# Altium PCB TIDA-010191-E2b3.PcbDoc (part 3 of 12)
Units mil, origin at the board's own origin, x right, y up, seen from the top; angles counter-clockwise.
Board outline 9842.52 x 9842.4 mil, 6 copper layers (Layer 1 - Top Layer, Layer 2 - GND Layer, Layer 3 - Signal, Layer 4 - Signal, Layer 5 - GND, Bottom Layer), stack 59.9 mil thick; 1178 components, 642 nets, 3329 pads, 2967 vias.
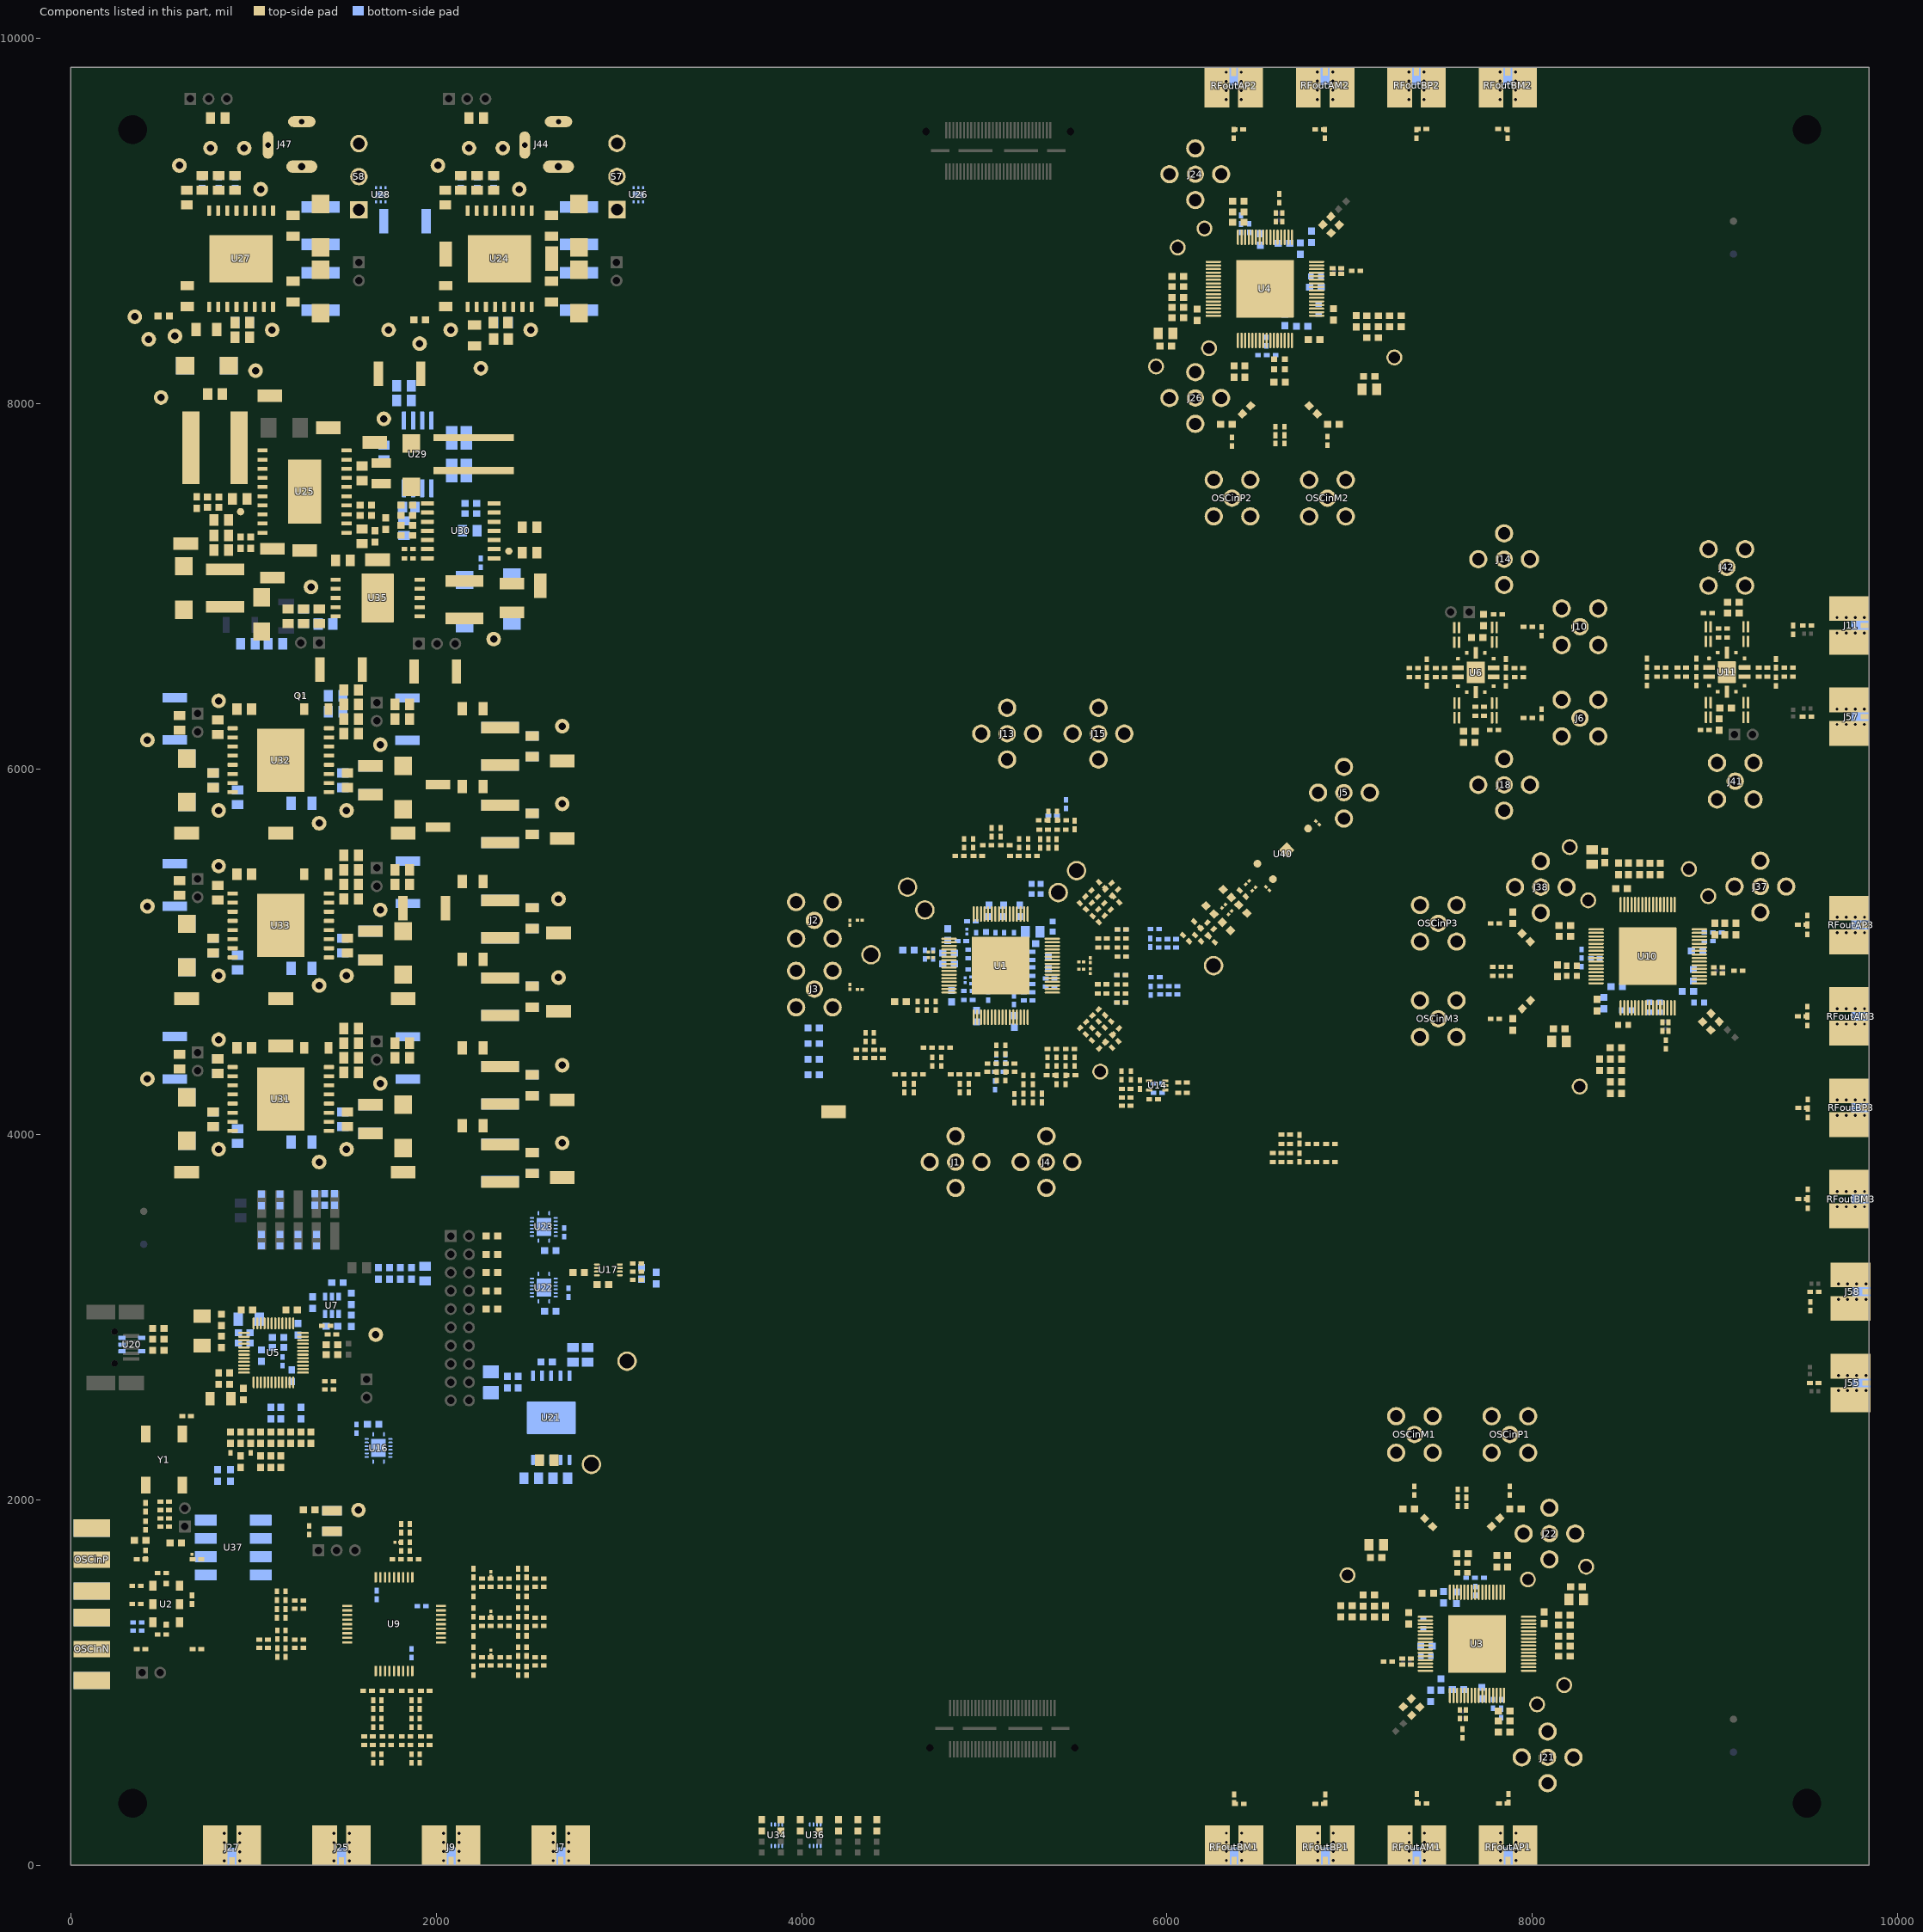
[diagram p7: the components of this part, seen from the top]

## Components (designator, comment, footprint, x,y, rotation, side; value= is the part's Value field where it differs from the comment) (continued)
OSCinP1 "142-0701-201" Johnson_142-0701-20x 7876.55,2358.61 r270 top
OSCinP2 "142-0701-201" Johnson_142-0701-20x 6355.8,7484.37 r90 top
OSCinP3 "CMP-0055819-1" Johnson_142-0701-20x 7484.87,5156.75 r0 top
Q1 "MMBT3904LP" DIODES_X1-DFN1006-3 1262.75,6401.42 r180 top value="40 V"
R1 "Resistor" 0402 5040,4344 r180 top value=0
R2 "Resistor" 0402 5425,5721 r0 top value=0
R3 "Resistor" 0402 5068,4320 r90 top value=0
R4 "Resistor" 0402 4915,4255 r270 top value=0
R5 "Resistor" 0402 5215,4300 r90 top value=120
R6 "Resistor" 0402 5115,4320 r90 top value=0
R7 "Resistor" 0402 4865,4255 r270 top value=0
R8 "Resistor" 0402 5215.21,4200.32 r270 top value=0
R9 "Resistor" 0402 5143,4344 r0 top value=0
R10 "Resistor" 0402 5322,5721 r180 top value=0
R11 "Resistor" 0402 5141,4390 r180 top value=240
R12 "Resistor" 0402 5041,4390 r0 top value=240
R13 "Resistor" 0402 5315.21,4200.32 r90 top value=120
R14 "Resistor" 0402 5165,4200 r90 top value=120
R15 "Resistor" 0402 4940,4330 r180 top value=240
R16 "Resistor" 0402 4840,4330 r0 top value=240
R17 "Resistor" 0402 4790,4475 r180 top value=220
R18 "Resistor" 0402 4690,4475 r0 top value=220
R19 "Resistor" 0402 4613,4255 r270 top value=0
R20 "Resistor" 0402 4563,4255 r270 top value=0
R21 "Resistor" 0402 5470,4470 r180 top value=120
R22 "Resistor" 0402 5370,4470 r0 top value=120
R23 "Resistor" 0402 4640.72,4331.16 r180 top value=240
R24 "Resistor" 0402 4535.72,4331.16 r0 top value=240
R25 "Resistor" 0402 5749.89,4773.09 r0 top value=0
R26 "CMP-0026822-3" 0402 5645.83,4488.44 r45 top value=0
R27 "Resistor" 0402 5750,4823 r0 top value=0
R28 "Resistor" 0201 4940,4826.66 r180 bottom value=620
R29 "Resistor" 0402 5749.89,4873.09 r180 top value=120
R30 "Resistor" 0402 5749.89,4723.09 r180 top value=120
R31 "Resistor" 0402 5608.61,4668.61 r225 top value=120
R32 "Resistor" 0402 5540.8,4600 r45 top value=120
R33 "Resistor" 0402 635,2460 r0 top value=0
R34 "Resistor" 0402 1175,1379 r270 top value=130
R35 "Resistor" 0402 5240,4735 r0 bottom value=10.0k
R36 "ERJ-2GE0R00X" 0402 1250,1405 r0 top value=0
R37 "Resistor" 0402 385,1183.92 r0 top value=0
R38 "ERJ-2GE0R00X" 0402 1250,1450 r0 top value=0
R39 "Resistor" 0402 385,1675 r0 top value=0
R40 "Resistor" 0402 1175,1476 r90 top value=130
R41 "Resistor" 0402 5751.89,5024.09 r0 top value=0
R42 "Resistor" 0402 5751.89,5074.09 r0 top value=0
R43 "Resistor" 0402 499.09,1263.12 r180 top value=12k
R44 "Resistor" 0402 500,1600 r180 top value=12k
R45 "Resistor" 0402 360,1530 r180 top value=0
R46 "Resistor" 0402 360,1430 r180 top value=0
R47 "Resistor" 0402 5540,5250 r315 top value=120
R48 "Resistor" 0402 5610,5180 r135 top value=120
R49 "Resistor" 0402 5751.89,5124.09 r180 top value=120
R50 "Resistor" 0402 5751.89,4974.09 r180 top value=120
R51 "Resistor" 0402 664.09,1454.12 r270 top value=12k
R52 "Resistor" 0201 4905,5111.3 r90 bottom value=39.0k
R53 "Resistor" 0603L 5010,5081.38 r270 bottom value=51
R54 "Resistor" 0402 5397,5745 r270 top value=0
R55 "Resistor" 0402 4890,5595 r90 top value=0
R56 "Resistor" 0402 5350,5745 r270 top value=0
R57 "Resistor" 0402 4940,5595 r90 top value=0
R58 "Resistor" 0402 5325,5670 r0 top value=220
R59 "Resistor" 0402 5423,5670 r180 top value=220
R60 "Resistor" 0402 4865,5525 r180 top value=240
R61 "Resistor" 0402 4965,5525 r0 top value=240
R62 "Resistor" 0402 5240,5595 r270 top value=0
R63 "Resistor" 0402 5190,5595 r270 top value=0
R64 "Resistor" 0402 5165,5525 r180 top value=240
R65 "Resistor" 0402 5265,5525 r0 top value=240
R66 "Resistor" 0402 5015,5585 r0 top value=240
R67 "Resistor" 0402 5115,5585 r180 top value=240
R68 "CMP-0026822-3" 0402 5682,4493 r135 top value=0
R69 "CMP-0026822-3" 0402 5720.91,4565.5 r225 top value=0
R70 "Resistor" 0402 4765,4400 r270 top value=0
R71 "CMP-0026822-3" 0402 5717,4528 r135 top value=0
R72 "CMP-0026822-3" 0402 6033.51,4767.92 r180 bottom value=0
R73 "CMP-0026822-3" 0402 6033.51,4812.92 r180 bottom value=0
R74 "CMP-0026822-3" 0402 5721.7,5287.74 r135 top value=0
R75 "CMP-0026822-3" 0402 5715,5325 r225 top value=0
R76 "CMP-0026822-3" 0402 5644.59,5365.44 r315 top value=0
R77 "Resistor" 0603 4066.89,4412 r180 bottom value=750
R78 "Resistor" 0603 4066.89,4328.46 r180 bottom value=750
R79 "Resistor" 0603 4066.89,4583.46 r180 bottom value=750
R80 "Resistor" 0603 4066.89,4498.46 r180 bottom value=750
R81 "CMP-0026822-3" 0402 5680,5360 r225 top value=0
R82 "CMP-0026791-1" 0402 7634.77,827.47 r270 top value=50
R83 "Resistor" 0603 7512.98,1467.65 r270 bottom value=0
R84 "CMP-0026822-3" 0402 6025.96,5025.26 r180 bottom value=0
R85 "Resistor" 0603L 7402.35,1322.98 r270 bottom value=0
R86 "CMP-0026791-1" 0402 7602.4,827.46 r90 top value=50
R87 "Resistor" 0603 7500,990 r270 bottom value=0
R88 "Resistor" 0603L 7416.87,1146.12 r180 bottom value=0
R89 "Resistor" 0603 7845,730 r0 top value=0
R90 "Resistor" 0603 7865,1665 r270 top value=100k
R91 "Resistor" 0603 8175,1370 r0 top value=0
R92 "CMP-0026822-3" 0402 6025.96,5070.26 r180 bottom value=0
R93 "CMP-0026791-1" 0402 7310.77,1131.8 r180 top value=50
R94 "Resistor" 0603 7105,1480 r180 top value=270
R95 "CMP-0025697-4" 0603 7105,1420 r180 top value=0
R96 "Resistor" 0603 6982.45,1360.54 r180 top value=120
R97 "CMP-0026791-1" 0402 7310.77,1099.43 r0 top value=50
R98 "CMP-0065361-1" 0201 4318.74,5174.45 r0 top value=0
R99 "RC0201JR-0751RL" 0201 4265,5160 r90 top value=51
R100 "RC0201JR-0751RL" 0201 4263.74,4809.72 r90 top value=51
R101 "CMP-0065361-1" 0201 4318.74,4793.74 r0 top value=0
R102 "CMP-0021991-4" 0603 7314.86,890.31 r225 top value=100
R103 "ERJ-1GN0R00C" 0201 6345,5215 r225 top value=0
R104 "Resistor" 0603 7907.35,1951.61 r0 top value=51
R105 "Resistor" 0603 7361.15,844.02 r45 top value=330
R106 "ERJ-1GN0R00C" 0201 6824,5706 r315 top value=0
R107 "Resistor" 0603 7798.75,1878.01 r225 top value=0
R108 "CRCW060349R9FKEA" 0603 6415,5235 r135 top value=49.9
R109 "CMP-0021991-4" 0603 7617.35,1705.61 r0 top value=100
R110 "CRCW060349R9FKEA" 0603 6325,5140 r135 top value=49.9
R111 "ERJ-1GN0R00C" 0201 6475,5345 r225 top value=0
R112 "Resistor" 0603 7431.75,1877.01 r135 top value=0
R113 "Resistor" 0603 7322.35,1951.61 r0 top value=51
R114 "Resistor" 0402 5675,5215 r45 top value=0
R115 "Resistor" 0402 5751.89,5124.09 r180 bottom value=0
R116 "CRCW0402100RFKED" 0402 6415,5320 r315 top value=100
R117 "ERJ-1GN0R00C" 0201 6440,5380 r225 top value=0
R118 "CRCW060349R9FKEA" 0603 6330,5320 r135 top value=49.9
R119 "CRCW060349R9FKEA" 0603 6235,5230 r135 top value=49.9
R120 "ERJ-1GN0R00C" 0201 6310,5250 r225 top value=0
R121 "CRCW040240R2FKED" 0402 7350,6505 r180 top value=40.2
R122 "CRCW0402200RFKED" 0402 7855,6480 r270 top value=200
R123 "CRCW04021K10JNED" 0402 8050,6305 r270 top value=1.1k
R124 "CRCW040212R1FKED" 0402 7926.31,6505 r180 top value=12.1
R125 "CRCW040212R1FKED" 0402 7925,6555 r180 top value=12.1
R126 "CMP-0026822-3" 0402 5365,4325 r0 top value=0
R127 "CMP-0026822-3" 0402 5395,4300 r90 top value=0
R128 "CRCW0402200RFKED" 0402 7855,6580 r90 top value=200
R129 "CRCW04021K10JNED" 0402 8050,6755 r90 top value=1.1k
R130 "CMP-0026822-3" 0402 5475,4325 r180 top value=0
R131 "CRCW040240R2FKED" 0402 7350,6555 r180 top value=40.2
R132 "CMP-0026822-3" 0402 5445,4300 r90 top value=0
R133 "CRCW04020000Z0ED" 0402 7811.31,6847.18 r180 top value=0
R134 "CRCW04020000Z0ED" 0402 7790,6215 r180 top value=0
R135 "CMP-0026822-3" 0402 6602.76,3850 r0 top value=0
R136 "CMP-0026822-3" 0402 6602.76,3900 r0 top value=0
R137 "CRCW06031K00FKEA" 0603 7654.31,6207.18 r0 top value=1.00k
R138 "CRCW060349R9FKEA" 0603 7698,6721 r180 top value=49.9
R139 "ERJ-2RKF1002X" 0402 7711.31,6292.18 r180 top value=10.0k
R140 "CRCW06031K00FKEA" 0603 7653.94,6146.75 r0 top value=1.00k
R141 "Resistor" 0402 5058.62,4269.47 r90 bottom value=0
R142 "Resistor" 0402 5936.27,4862.92 r180 bottom value=0
R143 "CRCW0402100RFKED" 0402 5080.9,4343.12 r180 bottom value=100
R144 "Resistor" 0402 6895,3950 r0 top value=0
R145 "CRCW0402100RFKED" 0402 6169.89,5075 r135 top value=100
R146 "Resistor" 0402 6650,3900 r0 top value=0
R147 "Resistor" 0603 1430,2795.59 r0 top value=39k
R148 "Resistor" 0402 6895,3850 r0 top value=0
R149 "Resistor" 0603 480,2880 r0 top value=10.0
R150 "Resistor" 0603 480,2820 r0 top value=10.0
R151 "Resistor" 0603 1095,2475.59 r90 bottom value=10k
R152 "Resistor" 0603 1150,2475.59 r90 bottom value=10k
R153 "CMP-0025711-4" 0603 1045,2790 r270 bottom value=12k
R154 "CMP-0021991-4" 0603 930,2340.59 r270 top value=100
R155 "CRCW04024K75FKED" 0402 1430,2905.59 r0 top value=4.75k
R156 "CMP-0021991-4" 0603 1040,2340.59 r270 top value=100
R157 "CMP-0021991-4" 0603 1095,2340.59 r270 top value=100
R158 "CMP-0021991-4" 0603 1150,2340.59 r270 top value=100
R159 "CMP-0021991-4" 0603 1205,2340.59 r270 top value=100
R160 "Resistor" 0603 1535,2980.59 r90 bottom value=10k
R161 "Resistor" 0603 1460,3190 r0 bottom value=10k
R162 "Resistor" 0603 1325,3080.59 r270 bottom value=10k
R163 "Resistor" 0603 1430,2950.59 r0 bottom value=2.0k
R164 "ERJ-1GN0R00C" 0201 6551,5347 r135 top value=0
R165 "Resistor" 0402 6650,3850 r0 top value=0
R166 "CMP-0026822-3" 0402 5986.27,4812.92 r0 bottom value=0
R167 "Resistor" 0402 6795,3950 r0 top value=0
R168 "CRCW0402100RFKED" 0402 6725,3875 r90 top value=100
R169 "CRCW0402100RFKED" 0402 5911.27,4787.92 r90 bottom value=100
R170 "CRCW0402100RFKED" 0402 410,1860 r90 top value=100
R171 "Resistor" 0603 380,1780 r0 top value=82.0
R172 "Resistor" 0402 875,2282 r270 top value=0
R173 "Resistor" 0402 986,2282 r270 top value=0
R174 "CRCW040210K0FKED" 0402 1398.5,2953.5 r0 top value=10.0k
R175 "ERJ-2RKF1002X" 0402 1305,1835 r90 top value=10.0k
R177 "CRCW040282R5FKED" 0402 1131,1262 r270 top value=82.5
R178 "Resistor" 0603 875,2340.59 r270 top value=0
R179 "CRCW040282R5FKED" 0402 1131,1165 r90 top value=82.5
R180 "ERJ-2GE0R00X" 0402 1250,1236 r0 top value=0
R181 "CMP-0021991-4" 0603 1260,2340.59 r270 top value=100
R182 "Resistor" 0402 4715,4400 r270 top value=0
R183 "Resistor" 0402 5040,5655 r90 top value=0
R184 "Resistor" 0402 5090,5655 r90 top value=0
R185 "CMP-0021991-4" 0603 930,2210 r270 top value=100
R186 "CMP-0021991-4" 0603 1040,2210 r270 top value=100
R187 "CMP-0021991-4" 0603 1095,2210 r270 top value=100
R188 "CMP-0021991-4" 0603 1150,2210 r270 top value=100
R189 "CMP-0021991-4" 0603 3205,3215 r90 bottom value=100
R190 "Resistor" 0402 5360,4855 r0 bottom value=47
R191 "Resistor" 0402 5950,4230 r0 bottom value=0
R192 "Resistor" 0402 6085,4230 r180 top value=0
R193 "Resistor" 0402 5851.89,4274.09 r270 top value=0
R194 "Resistor" 0402 6085,4285 r180 top value=0
R195 "Resistor" 0402 5950,4280 r0 bottom value=0
R196 "Resistor" 0402 5776.89,4159.09 r0 top value=0
R197 "Resistor" 0402 5776.89,4204.09 r180 top value=0
R198 "CRCW040282R5FKED" 0402 1130,1476 r270 top value=82.5
R199 "CRCW040282R5FKED" 0402 1130,1379 r90 top value=82.5
R200 "Resistor" 0402 5801.89,4324.09 r270 top value=0
R201 "Resistor" 0402 5776.89,4249.09 r180 top value=0
R202 "Resistor" 0402 5751.89,4324.09 r270 top value=0
R203 "CMP-0026822-3" 0402 5986.27,4767.92 r0 bottom value=0
R204 "CRCW0402100RFKED" 0402 5374,5746 r0 bottom value=100
R205 "Resistor" 0603 1260,2475.59 r90 bottom value=10k
R206 "CMP-0021991-4" 0603 1315,2340.59 r90 top value=100
R207 "CMP-0021991-4" 0603 2780,3245 r180 top value=100
R208 "CMP-0026822-3" 0402 5978.54,5070.08 r0 bottom value=0
R209 "CMP-0026822-3" 0402 5448,5809 r90 bottom value=0
R210 "ERJ-1GN0R00C" 0201 1788.01,1768 r180 top value=0
R211 "Resistor" 0603 1045,3642.56 r270 bottom value=0
R212 "Resistor" 0603 985,2340.59 r270 top value=0
R213 "Resistor" 0402 7784.74,883.8 r90 bottom value=10.0k
R214 "Resistor" 0402 7687.45,1501.92 r270 bottom value=10.0k
R215 "CRCW0402100RFKED" 0402 5908.54,5050.08 r90 bottom value=100
R216 "CMP-0026822-3" 0402 5933.54,5125.08 r180 bottom value=0
R217 "Resistor" 0603 1430,2850.59 r180 top value=1.00k
R218 "Resistor" 0402 3100,3250 r0 top value=0
R219 "Resistor" 0402 3100,3205 r0 top value=0
R220 "ERJ-2GE0R00X" 0402 1250,1191 r0 top value=0
R223 "Resistor" 0402 9503.48,5120.38 r270 top value=0
R224 "CMP-0026791-1" 0402 9016.02,4914.97 r0 top value=50
R225 "CMP-0021991-4" 0603 3125,3240 r270 bottom value=100
R226 "Resistor" 0603 8851,4785 r0 bottom value=0
R227 "Resistor" 0603 8391,4720 r90 bottom value=0
R228 "Resistor" 0603L 8516,4680 r0 bottom value=0
R229 "Resistor" 0402 9503.38,4677.38 r90 top value=0
R230 "CMP-0026791-1" 0402 9016.02,4882.6 r180 top value=50
R231 "Resistor" 0603L 8697.36,4697.07 r270 bottom value=0
R232 "Resistor" 0603 9113.48,5125.2 r90 top value=0
R233 "CMP-0026822-3" 0402 5978.54,5025.08 r0 bottom value=0
R234 "Resistor" 0402 7840.19,340 r180 top value=0
R235 "Resistor" 0603 7592.35,962.98 r180 bottom value=0
R236 "Resistor" 0402 7397.19,340 r0 top value=0
R237 "Resistor" 0402 6396.17,337.54 r0 top value=0
R238 "CMP-0026822-3" 0402 7638.35,2034.06 r90 top value=0
R239 "CMP-0026822-3" 0402 7637.82,1991.31 r270 top value=0
R240 "CMP-0026822-3" 0402 7876.55,2051.31 r90 top value=0
R241 "Resistor" 0402 6835.82,337.54 r180 top value=0
R242 "CMP-0026822-3" 0402 7590.47,2034.06 r90 top value=0
R243 "CMP-0026822-3" 0402 7590.47,1991.31 r270 top value=0
R244 "CMP-0026822-3" 0402 7354.35,2051.31 r90 top value=0
R245 "CMP-0026822-3" 0402 7827.82,882.91 r90 bottom value=0
R246 "CMP-0026822-3" 0402 7827.82,831.31 r270 bottom value=0
R247 "CMP-0026822-3" 0402 7660.55,1575.03 r180 bottom value=0
R248 "Resistor" 0402 6393.45,9502.98 r0 top value=0
R249 "CMP-0026822-3" 0402 7710.55,1575.03 r0 bottom value=0
R250 "Resistor" 0603 8177.2,5144.53 r0 top value=100k
R251 "Resistor" 0603 6730,8850 r90 bottom value=0
R252 "Resistor" 0603 6640,8880 r0 bottom value=0
R253 "Resistor" 0603 6058.61,8472.44 r180 top value=0
R254 "Resistor" 0603 6390,9110 r180 top value=0
R255 "Resistor" 0603L 6814.91,8697.44 r0 bottom value=0
R256 "Resistor" 0603L 6830,8520 r90 bottom value=0
R257 "Resistor" 0603 6740,8425 r180 bottom value=0
R258 "CMP-0026791-1" 0402 6596.33,9021.5 r90 top value=50
R259 "Resistor" 0603 8471,5455 r90 top value=0
R260 "CMP-0026791-1" 0402 6632,9021.5 r270 top value=50
R261 "CMP-0026791-1" 0402 8711.68,4590.97 r270 top value=50
R262 "Resistor" 0603 8427.12,4382.55 r270 top value=0
R263 "Resistor" 0603 8366.6,4382.55 r270 top value=270
R264 "Resistor" 0603 8486.6,4257.55 r270 top value=120
R265 "CMP-0026791-1" 0402 8744.05,4590.97 r90 top value=50
R266 "Resistor" 0402 9503.48,5175.87 r90 top value=0
R267 "Resistor" 0402 8344.23,4966.61 r0 bottom value=10.0k
R268 "Resistor" 0402 8964.69,5059.94 r180 bottom value=10.0k
R269 "CMP-0026822-3" 0402 8964.69,5107.5 r180 bottom value=0
R270 "Resistor" 0402 1176,1262 r90 top value=130
R271 "CMP-0026822-3" 0402 9011.93,5107.5 r0 bottom value=0
R272 "CMP-0026822-3" 0402 7853.17,4918.1 r0 top value=0
R273 "CMP-0026822-3" 0402 8269.61,4942.99 r270 bottom value=0
R274 "Resistor" 0603 6368.01,8176.71 r90 top value=100k
R275 "Resistor" 0402 6834.88,9502.98 r180 top value=0
R276 "Resistor" 0402 7836.19,9505.44 r180 top value=0
R277 "Resistor" 0603 7891.87,5187.55 r90 top value=51
R278 "Resistor" 0402 8269.61,4990.24 r90 bottom value=0
R279 "CMP-0021991-4" 0603 8953.17,4595.05 r315 top value=100
R280 "CMP-0026822-3" 0402 7794.87,5156.75 r180 top value=0
R281 "Resistor" 0603 7965.47,5078.95 r315 top value=0
R282 "Resistor" 0402 5115,4465 r90 top value=20.0
R283 "Resistor" 0402 5065,4465 r90 top value=20.0
R284 "Resistor" 0402 5572,4532 r315 top value=0
R285 "Resistor" 0402 5678,4637 r135 top value=0
R286 "Resistor" 0402 5644.59,4773.09 r180 top value=120
R287 "Resistor" 0402 5644.59,4823.09 r180 top value=120
R288 "Resistor" 0402 5646.89,5024.09 r180 top value=120
R289 "Resistor" 0402 5646.89,5074.09 r180 top value=120
R290 "Resistor" 0402 5749.89,4873.09 r180 bottom value=0
R291 "Resistor" 0402 5570,5320 r225 top value=0
R292 "Resistor" 0402 5396.3,5593.74 r270 top value=20.0
R293 "Resistor" 0402 5351.3,5593.74 r270 top value=20.0
R294 "Resistor" 0603 8999.46,4641.35 r135 top value=330
R295 "CMP-0026822-3" 0402 7806.24,4918.3 r180 top value=0
R296 "Resistor" 0603 1045,3422.56 r90 bottom value=33
R297 "Resistor" 0402 5749.89,4723.09 r0 bottom value=0
R298 "Resistor" 0402 5751.89,4974.09 r0 bottom value=0
R299 "Resistor" 0402 1176,1165 r270 top value=130
R300 "CMP-0021991-4" 0603 8137.87,4897.55 r90 top value=100
R301 "CMP-0026822-3" 0402 7806.24,4868.8 r180 top value=0
R302 "Resistor" 0603 1145,3422.56 r270 bottom value=33
R303 "Resistor" 0603 1345,3422.56 r270 bottom value=33
R304 "Resistor" 0603 1245,3422.56 r270 bottom value=0
R305 "Resistor" 0603 1335,3645 r90 bottom value=33
R306 "Resistor" 0603 1445,3645 r90 bottom value=33
R307 "Resistor" 0603 1145,3643.06 r90 bottom value=33
R308 "Resistor" 0603 2305,3445 r180 top value=10k
R309 "Resistor" 0603 2305,3345 r180 top value=10k
R310 "Resistor" 0603 2305,3245 r180 top value=10k
R311 "Resistor" 0603 1390,3645 r90 bottom value=33
R312 "Resistor" 0603 2305,3145 r180 top value=10k
R313 "CMP-0021991-4" 0603 6919.91,8957.44 r45 top value=100
R314 "Resistor" 0603 6874.91,9003.08 r225 top value=330
R315 "CMP-0026791-1" 0402 6929.91,8711.18 r0 top value=50
R316 "CMP-0026822-3" 0402 7794.87,4634.05 r180 top value=0
R317 "Resistor" 0603 7966.47,4711.95 r225 top value=0
R318 "Resistor" 0603 7891.87,4602.55 r90 top value=51
R319 "CMP-0026822-3" 0402 7853.17,4869.1 r0 top value=0
R320 "CMP-0025697-4" 0603 7124.91,8422.97 r0 top value=0
R321 "Resistor" 0603 7124.91,8362.44 r0 top value=270
R322 "Resistor" 0603 7249.91,8482.44 r0 top value=120
R323 "CRCW0402200RFKED" 0402 8897.02,6581.75 r90 top value=200
R324 "CRCW040212R1FKED" 0402 8817.02,6556.75 r0 top value=12.1
R325 "CMP-0026822-3" 0402 6594,7807.44 r270 top value=0
R326 "CRCW040212R1FKED" 0402 8817.02,6506.75 r0 top value=12.1
R327 "CMP-0026791-1" 0402 6929.91,8743.56 r180 top value=50
R328 "CRCW0402200RFKED" 0402 8897.02,6481.75 r270 top value=200
R329 "CRCW04021K10JNED" 0402 8627.02,6581.75 r270 top value=1.1k
R330 "CRCW04021K10JNED" 0402 8627.02,6481.75 r90 top value=1.1k
R331 "CMP-0026822-3" 0402 6594,7851.01 r90 top value=0
R332 "CMP-0026822-3" 0402 6355.94,7792.44 r270 top value=0
R333 "Resistor" 0603 6434.91,7967.44 r45 top value=0
R334 "CRCW040210K0DHEDP" 0402 6450,8962.24 r270 bottom value=10.0k
R335 "Resistor" 0402 5240,4870 r180 bottom value=0
R336 "Resistor" 0402 5315.21,4200.31 r270 bottom value=0
R337 "Resistor" 0402 5165,4200 r270 bottom value=0
R338 "Resistor" 0402 5495,4400 r270 top value=0
R339 "Resistor" 0402 5345,4400 r270 top value=0
R340 "Resistor" 0402 1160,2759.86 r270 bottom value=0
R341 "Resistor" 0402 1415,2650.59 r180 top value=0
R342 "CMP-0026769-2" 0402 6544.91,8341.06 r90 bottom value=10.0k
R343 "Resistor" 0402 5360,4810 r0 bottom value=10.0k
R344 "Resistor" 0402 5065,4415 r90 bottom value=0
R345 "Resistor" 0402 5115,4415 r270 bottom value=0
R346 "Resistor" 0402 5305,5594 r90 top value=0
R347 "Resistor" 0402 7395.88,9505.63 r0 top value=0
R348 "Resistor" 0603 6324.91,7888.07 r180 top value=51
R349 "CMP-0021991-4" 0603 6615.93,8118.88 r180 top value=100
R350 "CMP-0026822-3" 0402 6643.38,7807.44 r270 top value=0
R351 "Resistor" 0603 6910.37,7888.07 r180 top value=51
R352 "CMP-0026822-3" 0402 6643.38,7851.01 r90 top value=0
R353 "CMP-0026822-3" 0402 6878.64,7797.44 r270 top value=0
R354 "Resistor" 0603 6799.91,7967.44 r315 top value=0
R355 "CMP-0026822-3" 0402 6405,8962.24 r270 bottom value=0
R356 "Resistor" 0402 5265,4300 r90 top value=120
R357 "Resistor" 0402 5265.21,4200.32 r270 top value=0
R358 "CMP-0026822-3" 0402 6405,9008.62 r90 bottom value=0
R359 "CMP-0026822-3" 0402 6571.28,8267.44 r0 bottom value=0
R360 "CMP-0026822-3" 0402 6521.28,8267.44 r180 bottom value=0
R361 "ERJ-1GN0R00C" 0201 2299,1594 r90 top value=0
R362 "ERJ-1GN0R00C" 0201 665,1690 r90 top value=0
R363 "ERJ-1GN0R00C" 0201 2299,1378 r90 top value=0
R364 "ERJ-1GN0R00C" 0201 2298.62,1165 r90 top value=0
R366 "Resistor" 0402 5495,5695 r90 top value=0
R370 "Resistor" 0402 1415,2605 r180 top value=12k
R371 "Resistor" 0402 1565,2390 r270 bottom value=0
R372 "Resistor" 0603 8880.5,4872.55 r270 bottom value=0
R373 "CRCW040240R2FKED" 0402 9402.44,6556.75 r0 top value=40.2
R374 "CRCW040240R2FKED" 0402 9402.44,6506.75 r0 top value=40.2
R375 "CRCW04020000Z0ED" 0402 8942.44,6215.09 r0 top value=0
R376 "CRCW04020000Z0ED" 0402 8960,6855 r0 top value=0
R377 "CRCW06031K00FKEA" 0603 9100,6855 r180 top value=1.00k
R378 "CRCW060349R9FKEA" 0603 9057.44,6335.09 r0 top value=49.9
R379 "CRCW06031K00FKEA" 0603 9100,6915 r180 top value=1.00k
R380 "ERJ-2RKF1002X" 0402 9042.44,6770.09 r0 top value=10.0k
R381 "Resistor" 0402 3100,3295 r0 top value=0
R383 "CRCW06030000Z0EA" 0603 480,2940 r0 top value=0
R384 "ERJ-6GEY0R00V" 0805_HV 1450,6401.42 r180 bottom value=0
R385 "ERJ-6GEY0R00V" 0805_HV 1450,6315 r180 bottom value=0
R386 "CRCW080510K0JNEA" 0805_HV 2605,2217.44 r180 top value=10k
R387 "CRCW080510K0JNEA" 0805_HV 2750,2795 r90 bottom value=10k
R388 "CRCW0805750RJNEA" 0805_HV 2830,2795 r90 bottom value=750
R389 "CMP-0026822-3" 0402 2725,3135 r270 bottom value=0
R390 "Resistor" 0402 2700,3465 r270 bottom value=0
R391 "Resistor" 0402 6650,4000 r0 top value=0
R392 "CRCW0402100RFKED" 0402 6725,3975 r90 top value=100
R393 "Resistor" 0402 6650,3950 r0 top value=0
R394 "Resistor" 0402 6795,3850 r0 top value=0
R395 "CRCW040282R0JNED" 0402 1730,705 r0 top value=82
R396 "CRCW040282R0JNED" 0402 1630,705 r180 top value=82
R397 "ERJ-2GE0R00X" 0402 1700,880 r270 top value=0
R398 "ERJ-2GE0R00X" 0402 1700,585 r270 top value=0
R399 "ERJ-2GE0R00X" 0402 1655,880 r270 top value=0
R400 "ERJ-2GE0R00X" 0402 1655,585 r270 top value=0
R401 "CRCW0402150RFKED" 0402 1730,955 r180 top value=150
R402 "CRCW0402150RFKED" 0402 1625,955 r0 top value=150
R403 "CRCW0402130RFKED" 0402 1730,660 r180 top value=130
R404 "CRCW0402130RFKED" 0402 1630,660 r0 top value=130
R405 "Resistor" 0603 2305,3045 r180 top value=10k
R407 "KRL11050-C-R050-F-T1" 4320 2205,7725 r270 top value=0.05
R408 "RT0805BRD07100KL" 0805_HV 2220,9565 r0 top value=100k
R409 "Resistor" 0603 690,7460 r90 top value=49.9
R410 "RT0805BRD07100KL" 0805_HV 2050,9130 r270 top value=100k
R411 "Resistor" 0603 1725,7345 r90 top value=10.0k
R412 "Resistor" 0603 1615,7445 r0 top value=10.0k
R413 "Resistor" 0603 780,7435 r180 top value=10.1k
R414 "Resistor" 0603 1615,7390 r0 top value=95.3k
R415 "RT0603BRD072K84L" 0603 780,7490 r180 top value=2.84k
R416 "CRCW060310K7FKEA" 0603 2135,9210 r270 bottom value=10.7k
R417 "CRCW060311K5FKEA" 0603 2225,9210 r270 bottom value=11.5k
R418 "CRCW060330K9FKEA" 0603 2315,9210 r270 bottom value=30.9k
R419 "RT0603BRD077K59L" 0603 1910,8460 r0 top value=7.59k
R420 "Resistor" 0603 930,7240 r90 top value=2.26k
R421 "Resistor" 0603 1665,7275 r90 top value=3.40k
R422 "RMC1JPTE" 2512 1830,9000 r180 bottom value=0
R423 "RMC1JPTE" 2512 1800,8165 r0 top value=0
R424 "RT0805BRD07100KL" 0805_HV 805,9565 r0 top value=100k
R425 "RT0805BRD07100KL" 0805_HV 635,9130 r270 top value=100k
R426 "CRCW060310K7FKEA" 0603 720,9210 r270 bottom value=10.7k
R427 "CRCW060311K5FKEA" 0603 810,9210 r270 bottom value=11.5k
R428 "CRCW040282R0JNED" 0402 1941,705 r0 top value=82
R429 "CRCW040282R0JNED" 0402 1836,705 r180 top value=82
R430 "ERJ-2GE0R00X" 0402 1911,880 r270 top value=0
R431 "ERJ-2GE0R00X" 0402 1911,585 r270 top value=0
R432 "ERJ-2GE0R00X" 0402 1866,880 r270 top value=0
R433 "ERJ-2GE0R00X" 0402 1866,585 r270 top value=0
R434 "CRCW0402150RFKED" 0402 1941,955 r180 top value=150
R435 "CRCW0402150RFKED" 0402 1836,955 r0 top value=150
R436 "CRCW0402130RFKED" 0402 1941,660 r180 top value=130
R437 "CRCW0402130RFKED" 0402 1836,660 r0 top value=130
R438 "CRCW040282R0JNED" 0402 4324,4418.76 r180 top value=82
R439 "CRCW040282R0JNED" 0402 4421,4418.76 r0 top value=82
R440 "ERJ-2GE0R00X" 0402 1810,1745 r90 top value=0
R441 "ERJ-2GE0R00X" 0402 4350,4533.76 r90 top value=0
R442 "ERJ-2GE0R00X" 0402 1855,1745 r90 top value=0
R443 "ERJ-2GE0R00X" 0402 4395,4533.76 r90 top value=0
R444 "CRCW0402150RFKED" 0402 1784,1675 r0 top value=150
R445 "CRCW0402150RFKED" 0402 1881,1675 r180 top value=150
R446 "CRCW0402130RFKED" 0402 4324,4463.76 r0 top value=130
R447 "CRCW0402130RFKED" 0402 4421,4463.76 r180 top value=130
R448 "CRCW040282R0JNED" 0402 2450,1600 r90 top value=82
R449 "CRCW040282R0JNED" 0402 2450,1495 r270 top value=82
R450 "ERJ-2GE0R00X" 0402 2275,1570 r0 top value=0
R451 "ERJ-2GE0R00X" 0402 2565,1570 r0 top value=0
R452 "ERJ-2GE0R00X" 0402 2275,1525 r0 top value=0
R453 "ERJ-2GE0R00X" 0402 2565,1525 r0 top value=0
R454 "CRCW0402150RFKED" 0402 2205,1600 r270 top value=150
R455 "CRCW0402150RFKED" 0402 2205,1495 r90 top value=150
R456 "CRCW0402130RFKED" 0402 2495,1600 r270 top value=130
R457 "CRCW0402130RFKED" 0402 2495,1495 r90 top value=130
R458 "CRCW040282R0JNED" 0402 2450,1385 r90 top value=82
R459 "CRCW040282R0JNED" 0402 2450,1280 r270 top value=82
R460 "ERJ-2GE0R00X" 0402 2275,1355 r0 top value=0
R461 "ERJ-2GE0R00X" 0402 2565,1355 r0 top value=0
R462 "ERJ-2GE0R00X" 0402 2275,1310 r0 top value=0
R463 "ERJ-2GE0R00X" 0402 2565,1310 r0 top value=0
R464 "CRCW0402150RFKED" 0402 2205,1385 r270 top value=150
R465 "CRCW0402150RFKED" 0402 2205,1280 r90 top value=150
R466 "CRCW0402130RFKED" 0402 2495,1385 r270 top value=130
R467 "CRCW0402130RFKED" 0402 2495,1280 r90 top value=130
R468 "CRCW040282R0JNED" 0402 2450,1065 r270 top value=82
R469 "CRCW040282R0JNED" 0402 2450,1170 r90 top value=82
R470 "ERJ-2GE0R00X" 0402 2275,1095 r0 top value=0
R471 "ERJ-2GE0R00X" 0402 2565,1095 r0 top value=0
R472 "ERJ-2GE0R00X" 0402 2275,1140 r0 top value=0
R473 "ERJ-2GE0R00X" 0402 2565,1140 r0 top value=0
R474 "CRCW0402150RFKED" 0402 2205,1065 r90 top value=150
R475 "CRCW0402150RFKED" 0402 2205,1170 r270 top value=150
R476 "CRCW0402130RFKED" 0402 2495,1065 r90 top value=130
R477 "CRCW0402130RFKED" 0402 2495,1170 r270 top value=130
R478 "Resistor" 0402 9503.38,4620.26 r270 top value=0
R479 "CRCW060330K9FKEA" 0603 900,9210 r270 bottom value=30.9k
R480 "RT0603BRD077K59L" 0603 509,8481 r0 top value=7.59k
R481 "Resistor" 0402 9505.94,3621.26 r270 top value=0
R482 "Resistor" 0402 9505.94,3676.36 r90 top value=0
R483 "Resistor" 0402 9506.13,4169.5 r90 top value=0
R484 "Resistor" 0402 9506.13,4116.67 r270 top value=0
R485 "CRCW08050000Z0EA" 0805 1850,7435 r180 bottom value=0
R486 "Resistor" 0805_HV 2165,7635 r270 bottom value=0
R487 "Resistor" 0805_HV 2511,7325 r180 top value=20.0k
R488 "Resistor" 0805_HV 2511,7185 r180 top value=20.0k
R489 "Resistor" 0805_HV 2165,7815 r90 bottom value=0
R490 "Resistor" 0805_HV 2085,7815 r90 bottom value=0
R491 "Resistor" 0805_HV 2085,7635 r270 bottom value=0
R492 "RT0805BRD07352KL" 0805_HV 2185,7305 r0 bottom value=352k
R493 "RT0603BRD0710KL" 0603 2190,7455 r0 bottom value=10.0k
R494 "CMP-0026822-3" 0402 2245,7130 r90 bottom value=0
R495 "CRCW060310M0DHEAP" 0603 2190,7400 r0 bottom value=10Meg
R496 "RT0603BRD0710KL" 0603 1840,7390 r0 top value=10.0k
R497 "CMP-0026822-3" 0402 1850,7155 r0 top value=0
R498 "CRCW060310M0DHEAP" 0603 1840,7445 r0 top value=10Meg
R499 "RT0603BRD0710KL" 0603 1840,7280 r0 top value=10.0k
R500 "CMP-0026822-3" 0402 1850,7205 r0 top value=0
R501 "CRCW060310M0DHEAP" 0603 1840,7335 r0 top value=10Meg
R502 "RMC1JPTE" 2512 569.52,4420.24 r270 bottom value=0
R503 "RMC1JPTE" 2512 1845,4420 r270 bottom value=0
R504 "ERJ-8ENF3651V" 1206 1263.7,3959.17 r180 bottom value=3.65k
R505 "M55342K06B49D9T" 0805_HV 1815,4420 r0 top value=49.9
R506 "CRCW080520K0FKEA" 0805_HV 805,4375 r270 bottom value=20.0k
R507 "Resistor" 0805_HV 1490,4085 r270 bottom value=20.0k
R508 "PMR10EZPJ000" 0805_HV 805,4375 r270 top value=0
R509 "RT0805BRD0751K1L" 0805_HV 1535,4420 r0 top value=51.1k
R510 "PMR10EZPJ000" 0805_HV 595,4400 r270 top value=0
R511 "RT0805BRD0711K5L" 0805_HV 1535,4580 r180 top value=11.5k
R512 "RT0805BRD0711K5L" 0805_HV 913.15,3991.97 r90 bottom value=11.5k
R513 "M55342K06B49D9T" 0805_HV 1815,4500 r180 top value=49.9
R514 "RMC1JPTE" 2512 569.52,6276.26 r270 bottom value=0
R515 "RMC1JPTE" 2512 1843.62,6274.53 r270 bottom value=0
R516 "ERJ-8ENF3651V" 1206 1263.7,5813.7 r180 bottom value=3.65k
R517 "M55342K06B49D9T" 0805_HV 1815,6274.53 r0 top value=49.9
R518 "CMP-0021614-3" 0805_HV 1490,5940 r270 bottom value=20.0k
R519 "PMR10EZPJ000" 0805_HV 805,6229.53 r270 top value=0
R520 "RT0805BRD0751K1L" 0805_HV 1535,6274.53 r0 top value=51.1k
R521 "PMR10EZPJ000" 0805_HV 595,6254.53 r270 top value=0
R522 "RT0805BRD0711K5L" 0805_HV 1535,6434 r180 top value=11.5k
R523 "RT0805BRD0711K5L" 0805_HV 913.15,5846.5 r90 bottom value=11.5k
R524 "M55342K06B49D9T" 0805_HV 1815,6354.53 r180 top value=49.9
R525 "RMC1JPTE" 2512 2010,5800 r90 top value=0
R526 "RMC1JPTE" 2512 569.52,5366.73 r270 bottom value=0
R527 "RMC1JPTE" 2512 1844.52,5381.73 r270 bottom value=0
R528 "RMC1JPTE" 2512 1935,5240 r0 top value=0
R529 "ERJ-8ENF3651V" 1206 1263.7,4909.17 r180 bottom value=3.65k
R530 "M55342K06B49D9T" 0805_HV 1815,5370 r0 top value=49.9
R531 "CMP-0021614-3" 0805_HV 1490,5035 r270 bottom value=20.0k
R532 "PMR10EZPJ000" 0805_HV 805,5325 r270 top value=0
R533 "RT0805BRD0751K1L" 0805_HV 1535,5370 r0 top value=51.1k
R534 "PMR10EZPJ000" 0805_HV 595,5350 r270 top value=0
R535 "RT0805BRD0711K5L" 0805_HV 1535,5530 r180 top value=11.5k
R536 "RT0805BRD0711K5L" 0805_HV 913.15,4941.97 r90 bottom value=11.5k
R537 "M55342K06B49D9T" 0805_HV 1815,5450 r180 top value=49.9
R538 "CMP-0021991-4" 0603 3782.19,220 r270 top value=100
R539 "CMP-0021991-4" 0603 3887.19,220 r270 top value=100
R540 "CMP-0021991-4" 0603 3992.19,220 r270 top value=100
R541 "CMP-0021991-4" 0603 4097.19,220 r270 top value=100
R542 "RC0603FR-07178RL" 0603 4202.19,220 r90 top value=178
R543 "RC0603FR-07178RL" 0603 4307.19,220 r90 top value=178
R544 "RC0603FR-07178RL" 0603 4412.19,220 r90 top value=178
R545 "RMC1JPTE" 2512 1995,6535 r0 top value=0
R546 "RMC1JPTE" 2512 1480,6545 r180 top value=0
R547 "RT0805BRD0749R9L" 0805_HV 1190,6837.56 r90 top value=49.9
R548 "RT0805BRD078K66L" 0805_HV 1275,6837.56 r270 top value=8.66k
R549 "PMR10EZPJ000" 0805_HV 1120,6687.56 r180 bottom value=0
R550 "RT0805BRD073K2L" 0805_HV 1275,6837.56 r90 bottom value=3.20k
R551 "PMR10EZPJ000" 0805_HV 970,6687.56 r0 bottom value=0
R552 "RT0805BRD0749R9L" 0805_HV 1395,6795 r180 bottom value=49.9
R553 "ERJ-1GN0R00C" 0201 5530,4905 r180 top value=0
R554 "ERJ-1GN0R00C" 0201 5530,4945 r180 top value=0
R555 "ERJ-1GN0R00C" 0201 5580,4895 r270 top value=0
R556 "ERJ-1GN0R00C" 0201 5580,4955 r90 top value=0
R557 "CRCW080510K0JNEA" 0805_HV 2520,2120 r180 bottom value=10k
R558 "CRCW080510K0JNEA" 0805_HV 2680,2120 r0 bottom value=10k
R559 "Resistor" 0603 804.71,2135 r270 bottom value=0
R560 "Resistor" 0603 875,2135 r270 bottom value=0
RFoutAM1 "142-0771-831" Johnson_142-0771-831 7367.17,1.42 r180 top
RFoutAM2 "142-0771-831" Johnson_142-0771-831 6865.19,9841.56 r0 top
RFoutAM3 "142-0771-831" Johnson_142-0771-831 9842.06,4647.36 r270 top
RFoutAP1 "142-0771-831" Johnson_142-0771-831 7867.1,1.42 r180 top
RFoutAP2 "142-0771-831" Johnson_142-0771-831 6365,9840.55 r0 top
RFoutAP3 "142-0771-831" Johnson_142-0771-831 9842.06,5147.3 r270 top
RFoutBM1 "142-0771-831" Johnson_142-0771-831 6367.17,1.42 r180 top
RFoutBM2 "142-0771-831" Johnson_142-0771-831 7865.19,9841.56 r0 top
RFoutBM3 "142-0771-831" Johnson_142-0771-831 9842.06,3647.36 r270 top
RFoutBP1 "142-0771-831" Johnson_142-0771-831 6867.17,1.42 r180 top
RFoutBP2 "142-0771-831" Johnson_142-0771-831 7365.19,9841.56 r0 top
RFoutBP3 "142-0771-831" Johnson_142-0771-831 9842.06,4147.36 r270 top
RMPCLK1 "5007" Keystone5007 8025.51,881.14 r270 top
RMPCLK2 "5007" Keystone5007 6205,8960 r90 top
RMPCLK3 "5007" Keystone5007 8962.34,5305.7 r0 top
RMPDIR1 "5007" Keystone5007 8173.74,986.91 r270 top
RMPDIR2 "5007" Keystone5007 6058.61,8856.08 r90 top
RMPDIR3 "5007" Keystone5007 8856.58,5453.94 r0 top
S1 "Nut" TCBS-6-01 340,340 r0 top
S2 "Nut" TCBS-6-01 340,9502 r0 top
S3 "Nut" TCBS-6-01 9502,9502 r0 top
S4 "Nut" TCBS-6-01 9502,340 r0 top
S7 "CMP-0002125-2" "SW_ L101011MS02Q" 3102.56,9245 r180 top
S8 "CMP-0002125-2" "SW_ L101011MS02Q" 1690.06,9243.9 r180 top
SH-J1 "SPC02SYAN" SPC02SYAN 625,1905.19 r90 top value=1x2
SH-J2 "SPC02SYAN" SPC02SYAN 1406,1725 r180 top value=1x2
SH-J3 "SPC02SYAN" SPC02SYAN 2120,9670 r0 top value=1x2
SH-J4 "SPC02SYAN" SPC02SYAN 705,9670 r180 top value=1x2
SH-J30 "SPC02SYAN" SPC02SYAN 440,1055 r180 top value=1x2
SYNC "5007" Keystone5007 5635,4345 r180 top
TP1 "1573-2" Keystone1573-2 6255,4925 r270 top
TP2 "1573-2" Keystone1573-2 5405,5325 r270 top
TP3 "1573-2" Keystone1573-2 5505,5445 r270 top
TP4 "1573-2" Keystone1573-2 4580,5355 r0 top
TP5 "5015" Testpoint_Keystone_Miniature 4175,4125 r0 top
TP8 "5000" Keystone5000 1575,1945 r90 top
TP9 "1573-2" Keystone1573-2 2850,2195 r0 top
TP10 "1573-2" Keystone1573-2 3045,2760 r0 top
TP11 "5002" Keystone5002 2455,9175 r270 top
TP12 "5000" Keystone5000 2517.56,8405 r270 top
TP13 "5000" Keystone5000 495,8035 r270 top
TP14 "TP_SM_1MM" TP_SM_1MM 930,7410 r180 top
TP15 "5002" Keystone5002 2180,9400 r0 top
TP16 "5002" Keystone5002 2245,8195 r270 top
TP17 "5002" Keystone5002 1740,8405 r0 top
TP18 "5002" Keystone5002 2010,9305 r0 top
TP19 "5002" Keystone5002 2080,8405 r270 top
TP20 "5002" Keystone5002 1910,8330 r270 top
TP21 "5002" Keystone5002 2365,9400 r270 top
TP22 "5015" Testpoint_Keystone_Miniature 1090,8045 r0 top
TP23 "5015" Testpoint_Keystone_Miniature 2052.56,8820 r270 top
TP24 "5015" Testpoint_Keystone_Miniature 2632.56,8795 r270 top
TP25 "5015" Testpoint_Keystone_Miniature 1665,7789.09 r180 top
TP26 "5015" Testpoint_Keystone_Miniature 1410,7870 r180 top
TP27 "5002" Keystone5002 1040,9175 r0 top
TP28 "5000" Keystone5000 1102.94,8405 r0 top
TP29 "5002" Keystone5002 765,9400 r0 top
TP30 "5002" Keystone5002 1012,8182 r90 top
TP31 "5002" Keystone5002 351,8477 r0 top
TP32 "5002" Keystone5002 595,9305 r0 top
TP33 "5002" Keystone5002 571,8371 r0 top
TP34 "5002" Keystone5002 427,8354 r0 top
TP35 "5002" Keystone5002 950,9400 r0 top
TP36 "5015" Testpoint_Keystone_Miniature 1280,7197.56 r180 top
TP37 "5002" Keystone5002 1714.09,7918.58 r0 top
TP38 "TP_SM_1MM" TP_SM_1MM 2398,7194 r0 top
TP39 "5000" Keystone5000 1695,4280 r0 top
TP40 "5000" Keystone5000 420,4305 r0 top
TP41 "5000" Keystone5000 2690,4380 r0 top
TP42 "5002" Keystone5002 1510,3920 r0 top
TP43 "5015" Testpoint_Keystone_Miniature 2690,4190 r180 top
TP44 "5002" Keystone5002 1360,3850 r0 top
TP45 "5002" Keystone5002 810,3920 r0 top
TP46 "5000" Keystone5000 2690,3955 r0 top
TP47 "5002" Keystone5002 810,4520 r0 top
TP48 "5015" Testpoint_Keystone_Miniature 2690,3765 r180 top
TP49 "5015" Testpoint_Keystone_Miniature 1150,4485.47 r180 top
TP50 "5015" Testpoint_Keystone_Miniature 1820,3795 r180 top
TP51 "5015" Testpoint_Keystone_Miniature 635,3795 r0 top
TP52 "5000" Keystone5000 1695,6134.53 r90 top
TP53 "5000" Keystone5000 420,6160 r0 top
TP54 "5000" Keystone5000 2690,6235.79 r0 top
TP55 "5002" Keystone5002 1510,5774.53 r0 top
TP56 "5015" Testpoint_Keystone_Miniature 2690,6045.79 r180 top
TP57 "5002" Keystone5002 1360,5704.53 r0 top
TP58 "5002" Keystone5002 810,5774.53 r0 top
TP59 "5000" Keystone5000 2690,5810.79 r180 top
TP60 "5002" Keystone5002 810,6374.53 r180 top
TP61 "5015" Testpoint_Keystone_Miniature 2690,5620.79 r0 top
TP62 "5015" Testpoint_Keystone_Miniature 1150,5649.53 r180 top
TP63 "5015" Testpoint_Keystone_Miniature 1820,5649.53 r180 top
TP64 "5015" Testpoint_Keystone_Miniature 635,5649.53 r180 top
TP65 "5000" Keystone5000 1695,5230 r0 top
TP66 "5000" Keystone5000 420,5250 r0 top
TP67 "5000" Keystone5000 2670,5290 r0 top
TP68 "5002" Keystone5002 1510,4870 r0 top
TP69 "5015" Testpoint_Keystone_Miniature 2670,5105 r180 top
TP70 "5002" Keystone5002 1360,4817 r0 top
TP71 "5002" Keystone5002 810,4870 r0 top
TP72 "5000" Keystone5000 2670,4860 r0 top
TP73 "5002" Keystone5002 810,5470 r90 top
TP74 "5015" Testpoint_Keystone_Miniature 2670,4675 r180 top
TP75 "5015" Testpoint_Keystone_Miniature 1150,4745 r180 top
TP76 "5015" Testpoint_Keystone_Miniature 1820,4745 r180 top
TP77 "5015" Testpoint_Keystone_Miniature 635,4745 r180 top
TP78 "5000" Keystone5000 2315,6712.56 r180 top
TP79 "5000" Keystone5000 1315,6997.56 r180 top
TP80 "5015" Testpoint_Keystone_Miniature 630,7235 r0 top
TP81 "5015" Testpoint_Keystone_Miniature 1680,7147.56 r180 top
TP82 "5015" Testpoint_Keystone_Miniature 2570,7005 r270 top
TP83 "1573-2" Keystone1573-2 4380,4985 r0 top
TP84 "1573-2" Keystone1573-2 4675,5230 r0 top
U1 "LMK04832W-MLS" HBE0064A-MFG 5090,4925 r180 top locked
U2 "CMP-0075884-1" SIA0008B 523.19,1430.27 r180 top
U3 "LMX2615W-MLS" HBD0064A_Custom_A 7696.26,1212.95 r270 top locked
U4 "LMX2615W-MLS" HBD0064A_Custom_A 6536.09,8630.03 r90 top
U5 "FT232HL-REEL" LQFP-48_N 1110,2805.59 r0 top
U6 "LMH5401FFK/EM" FFK0014A 7690,6530 r90 top
U7 "93LC56BT-I/OT" SOT-23-6 1430,3065.59 r90 bottom
U9 "CDCLVP111HFG/EM" HFG0036A_Custom_A 1770.08,1320.48 r0 top
U10 "LMX2615W-MLS" HBD0064A_Custom_A 8630.53,4976.46 r0 top locked
U11 "LMH5401FFK/EM" FFK0014A 9063.94,6531.75 r270 top
U14 "SN74LVC1G08DCKR" DCK0005A_N 5946.89,4269.09 r180 top
U16 "SN74CBTLV3257RGYR" RGY0016A 1685,2285 r180 bottom
U17 "TS5A3357QDCURQ1" DCU0008A_N 2942.92,3260 r180 top
U20 "ESDS302DBVR" DBV0005A_N 335,2851 r0 bottom
U21 "TMP461HKU/EM" HKU0010_CUSTOM_A#1 2630,2450 r270 bottom
U22 "SN74CBTLV3257RGYR" RGY0016A 2590,3162.56 r0 bottom
U23 "SN74CBTLV3257RGYR" RGY0016A 2590,3495 r0 bottom
U24 "TPS7H2201HKR/EM" HKR0016A_Custom_A 2347.56,8795 r270 top
U25 "TPS50601AHKH/EM" HKH0020A_CUSTOM_A 1280,7520 r180 top
U26 "TVS0500DRVR" DRV0006A 3107.56,9145 r270 bottom
U27 "TPS7H2201HKR/EM" HKR0016A_Custom_A 932.56,8795 r270 top
U28 "TVS0500DRVR" DRV0006A 1697.56,9145 r270 bottom
U29 "INA901HKX/EM" HKX0008A_Custom_A 1899.09,7723.58 r90 bottom
U30 "LM139AWGRLQMLV" NAC0014A_L 2135,7305 r180 top
U31 "TPS7H1101AHKR/EM" HKR0016A_Custom_A 1150,4195 r0 top
U32 "TPS7H1101AHKR/EM" HKR0016A_Custom_A 1150,6049.53 r0 top
U33 "TPS7H1101AHKR/EM" HKR0016A_Custom_A 1150,5145 r0 top
U34 "SN74LVC3G06DCUR" DCU0008A_L 3865,165 r270 bottom
U35 "TPS7A4501HKU/EM" HKU0010_CUSTOM_A#2 1680,6937.56 r180 top
U36 "SN74LVC3G06DCUR" DCU0008A_L 4075,165 r270 bottom
U37 "AD4PS-1+" FP-AD4PS-1+_SMT8-MFG 890,1740 r0 bottom
U40 "BAL-0006SMG" Marki_BAL-0006SMG 6654.68,5558.22 r315 top
Vcc_TP1 "5007" Keystone5007 8294,1635 r0 top
Vcc_TP2 "5007" Keystone5007 5940,8205 r180 top
Vcc_TP3 "5007" Keystone5007 8204,5574 r90 top
VCCCORE "5000" Keystone5000 1670,2905 r270 top
Vtune_TP1 "5007" Keystone5007 6988.06,1588.51 r0 top
Vtune_TP2 "5007" Keystone5007 7244.3,8254.48 r180 top
Vtune_TP3 "5007" Keystone5007 8258.64,4263.16 r90 top
Y1 "CMP-0006073-3" OSC_CVHD-950-4 511.26,2221.3 r270 top
Y2 "ABM3-12.000MHZ-D2Y-T" XTAL_ABM3 720,2925.59 r270 top
ZZ1 "This Assembly Note is for PCB labels only" AssemblyNoteLabel 200,10700 r0 top
ZZ2 "These assemblies are ESD sensitive, ESD precautions shall be observed." AssemblyNote 200,10600 r0 top
ZZ3 "These assemblies must be clean and free from flux and all contaminants. Use of no clean flux is not acceptable." AssemblyNote 200,10500 r0 top
ZZ4 "These assemblies must comply with workmanship standards IPC-A-610 Class 2, unless otherwise specified." AssemblyNote 200,10400 r0 top

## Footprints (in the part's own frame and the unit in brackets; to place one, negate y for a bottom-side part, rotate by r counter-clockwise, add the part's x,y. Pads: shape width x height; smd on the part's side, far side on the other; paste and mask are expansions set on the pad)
0201 [mm] "Data from Kemet datasheet CC101_COM dated 7/28/11"
  rect 0.46x0.42 smd mask+0.048: 1(-0.33,0) 2(0.33,0)
  body extent -0.31,-0.16 0.31,0.16, height 0.26
0201_033 [mm] "SMD, 2-Leads, Height 0.33mm"
  rect 0.46x0.42 smd mask+0.048: 1(-0.33,0) 2(0.33,0)
  body extent -0.31,-0.16 0.31,0.16, height 0.33
0306 [mm] "based on TDK recommendation (similar to Taiyo Yuden and MuRata)"
  rrect29% 0.35x1.6 smd: 1(-0.325,0) 2(0.325,0)
  body extent -0.44,-0.85 0.44,0.85, height 0.6
0402 [mm] "0402 from SM-752 data"
  rect 0.8x0.6 smd: 1(-0.6,0) 2(0.6,0)
  silkscreen extent -1.22,-0.52 1.22,0.52, body extent -0.55,-0.3 0.55,0.3, height 0.6
0402_065 [mm] "0402"
  rect 0.8x0.6 smd: 1(-0.6,0) 2(0.6,0)
  silkscreen extent -1.22,-0.52 1.22,0.52, body extent -0.55,-0.3 0.55,0.3, height 0.65
0603 [mm] "0603 from SM-752 data"
  rect 1x0.95 smd: 1(-0.8,0) 2(0.8,0)
  silkscreen extent -1.52,-0.69 1.52,0.69, body extent -0.87,-0.47 0.87,0.47, height 1
0603L [mm] "0603 from SM-752 data"
  rect 0.8x0.85 smd: 1(-0.7,0) 2(0.7,0)
  silkscreen extent -0.07,-0.33 0.07,0.33, body extent -0.87,-0.47 0.87,0.47, height 1
0805 [mm] "0805 from SM-752 data"
  rect 1.3x1.5 smd: 1(-0.85,0) 2(0.85,0)
  silkscreen extent -1.72,-0.97 1.72,0.97, body extent -1.1,-0.72 1.1,0.72, height 1.45
0805_HV [mil] "0805 with 30mil clearance between pads"
  rect 50x63 smd: 1(-40,0) 2(40,0)
  silkscreen extent -74,-40 74,40, body extent -43,-29 43,29, height 57
1206 [mm] "1206 from SM-752 data"
  rect 1.3x1.85 smd: 1(-1.45,0) 2(1.45,0)
  silkscreen extent -2.4,-1.21 2.4,1.21, body extent -1.7,-0.9 1.7,0.9, height 1.35
1206_180 [mm] "1206_180"
  rect 1.1x1.6 smd: 1(-1.7,0) 2(1.7,0)
  silkscreen extent -0.9,-1 0.9,1, body extent -1.75,-0.95 1.75,0.95, height 1.8
1210 [mm] "1210 from SM-752 data"
  rect 1.3x2.7 smd: 1(-1.45,0) 2(1.45,0)
  silkscreen extent -2.32,-1.57 2.32,1.57, body extent -1.7,-1.35 1.7,1.35, height 1.35
1210_210 [mm] "1210"
  rect 1.3x2.7 smd: 1(-1.45,0) 2(1.45,0)
  silkscreen extent -2.32,-1.57 2.32,1.57, body extent -1.7,-1.35 1.7,1.35, height 2.1
1210_270 [mm] "1210"
  rect 1.3x2.7 smd: 1(-1.45,0) 2(1.45,0)
  silkscreen extent -2.32,-1.57 2.32,1.57, body extent -1.7,-1.35 1.7,1.35, height 2.7
1812_220 [mm] "1812"
  rect 1.6x3.4 smd: 1(-2,0) 2(2,0)
  silkscreen extent -0.8,-1.6 0.8,1.6, body extent -2.4,-1.7 2.4,1.7, height 2.2
1812_254 [mm] "SMD, 2-Leads, Body 4.8x3.4mm"
  rect 1.6x3.4 smd: 1(-2,0) 2(2,0)
  silkscreen extent -0.8,-1.7 0.8,1.7, body extent -2.4,-1.7 2.4,1.7, height 2.54
2220_280 [mm] "Chip Capacitor, Body 5.7x5.0mm, IPC Medium Density"
  rect 1.6x5.3 smd: 1(-2.6,0) 2(2.6,0)
  silkscreen extent -3.69,-2.94 3.69,2.94, body extent -2.95,-2.62 2.95,2.62, height 2.8
2220_310 [mm] "2220"
  rect 1.6x5.3 smd: 1(-2.6,0) 2(2.6,0)
  silkscreen extent -3.69,-2.94 3.69,2.94, body extent -2.95,-2.62 2.95,2.62, height 3.1
2512 [mm] "Chip Resistor, Body 6.3x3.2mm, IPC Medium Density"
  rect 1.3x3.4 smd: 1(-2.95,0) 2(2.95,0)
  silkscreen extent -1.9,-1.6 1.9,1.6, body extent -3.22,-1.67 3.22,1.67, height 0.71
3528-21 [mm] "Medium Density IPC, based on Kemet datasheet 2016-10-20"
  rrect6% 1.8x2.23 smd: 1(-1.46,0) 2(1.46,0)
  silkscreen extent -2.29,-1.5 0.76,1.5, body extent -1.85,-1.5 1.85,1.5, height 2.12
4320 [mm] "SUSUMU"
  rect 1x11.2 smd: 1(-2.3,0) 2(2.3,0)
  silkscreen extent -1.5,-5.7 1.5,5.7, body extent -2.6,-5.6 2.6,5.6, height 0.7
6032-28 [mm] "Medium Density IPC based on Vishay Sprague 293D datasheet."
  rect 2.55x2.3 smd: 1(-2.375,0) 2(2.375,0)
  silkscreen extent -3.96,-1.75 3.2,1.83, body extent -3.15,-1.75 3.15,1.75, height 2.8
7343-31 [mm] "Medium Density based on Kemet T495 dimensions"
  rect 2.55x2.45 smd: 1(-3.025,0) 2(3.025,0)
  silkscreen extent -4.56,-2.3 3.8,2.3, body extent -3.8,-2.3 3.8,2.3, height 3.1
7343-43 [mm] "Medium density IPC based on Kemet T495 series"
  rect 2.55x2.45 smd: 1(-3.025,0) 2(3.025,0)
  silkscreen extent -4.56,-2.3 3.8,2.3, body extent -3.8,-2.3 3.8,2.3, height 4.3
AE611PYA_1011 [mm] "Coilcraft"
  rect 2.38x10.11 smd: 1(-3.325,0) 2(3.325,0)
  silkscreen extent -5.3,-5.95 5.3,5.95, body extent -5.25,-5.9 5.25,5.9, height 10.05
AssemblyNote [mil] "Assembly Note"
AssemblyNoteLabel [mil] "Assembly Note for PCB Labels"
CONN_RAPC722X [mm] "Conn_DC Jack"
  oval 1.7x4.3 hole 1.01 slot 3.56 at 90 deg: 1(-13.741,0)
  oval 1.5x3.8 hole 0.76 slot 3.05 at 90 deg: 2(-7.493,0)
  oval 3.8x1.5 hole 0.76 slot 3.05 at 0 deg: 3(-10.744,4.7)
  silkscreen extent -14.48,-4.57 0.25,4.57, body extent -14.5,-4.57 0.23,4.83, height 11.18
DBV0005A_N [mm] "SOT23, 5-Leads, Body 2.9x1.6mm, Pitch 0.95mm, Lead Span 2.8mm, IPC Medium Density"
  rrect17% 1x0.6 smd: 1(-1.375,0.95) 2(-1.375,0) 3(-1.375,-0.95) 4(1.375,-0.95) 5(1.375,0.95)
  silkscreen extent -1.63,-1.55 0.38,1.55, body extent -1.42,-1.46 1.42,1.46, height 1.09
DCK0005A_N [mm] "SOT353, 5-Leads, Body 2x1.3mm, Pitch 0.65mm, Lead Span 2.1mm, IPC Medium Density"
  rrect25% 0.85x0.4 smd: 1(-1.125,0.65) 2(-1.125,0) 3(-1.125,-0.65) 4(1.125,-0.65) 5(1.125,0.65)
  silkscreen extent -1.48,-1.02 0.55,1.1, body extent -1.14,-1 1.14,1, height 0.95
DCU0008A_L [mm] "TSSOP, 8-Leads, Body 2x2.3mm, Pitch 0.5mm, IPC High Density"
  oval 0.6x0.25 smd: 1(-1.5,0.75) 2(-1.5,0.25) 3(-1.5,-0.25) 4(-1.5,-0.75) 5(1.5,-0.75) 6(1.5,-0.25) 7(1.5,0.25) 8(1.5,0.75)
  silkscreen extent -1.05,-1.05 0.38,1.05, body extent -1.56,-1 1.56,1, height 0.9
DCU0008A_N [mm] "TSSOP, 8-Leads, Body 2x2.3mm, Pitch 0.5mm, IPC Medium Density"
  oval 0.8x0.3 smd: 1(-1.6,0.75) 2(-1.6,0.25) 3(-1.6,-0.25) 4(-1.6,-0.75) 5(1.6,-0.75) 6(1.6,-0.25) 7(1.6,0.25) 8(1.6,0.75)
  silkscreen extent -1.05,-1.05 0.38,1.05, body extent -1.56,-1 1.56,1, height 0.9
DIODES_X1-DFN1006-3 [mm] "Diodes Recommended"
  rect 0.4x0.25 smd: 1(-0.35,0.225) 2(-0.35,-0.225)
  rect 0.4x0.7 smd: 3(0.35,0)
  silkscreen extent -0.87,-0.38 -0.69,0.38, body extent -0.54,-0.34 0.54,0.34, height 0.53
DRV0006A [mm] "SON, 6-Leads, Body 2x2mm, Pitch 0.65mm, Thermal Pad 1.6x1mm, TI Recommended"
  rrect33% 0.45x0.3 smd: 1(-0.975,0.65) 2(-0.975,0) 3(-0.975,-0.65) 4(0.975,-0.65) 5(0.975,0) 6(0.975,0.65)
  rrect14% 1x0.7 on Bottom Paste: 7(0,-0.45) 7(0,0.45)
  rrect10% 1x1.6 smd paste-0.5: 7(0,0)
  silkscreen extent -1.05,-1.2 1.05,1.2, body extent -1.05,-1.05 1.05,1.05, height 0.81
Emerson_142-0701-851 [mil] "Cinch Connectivity"
  rect 90x200 smd: 1(0,-110)
  rect 95x200 smd: 2(-172.5,-110) 3(172.5,-110)
  rect 95x200 smd far side: 4(172.5,-110) 5(-172.5,-110)
  silkscreen extent -235,-220 235,0, body extent -190,-195 190,387, height 155
ESD_Overlay_Small [mil]
  silkscreen extent -62,-48 64,61
FCC_disclaimer [mil]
